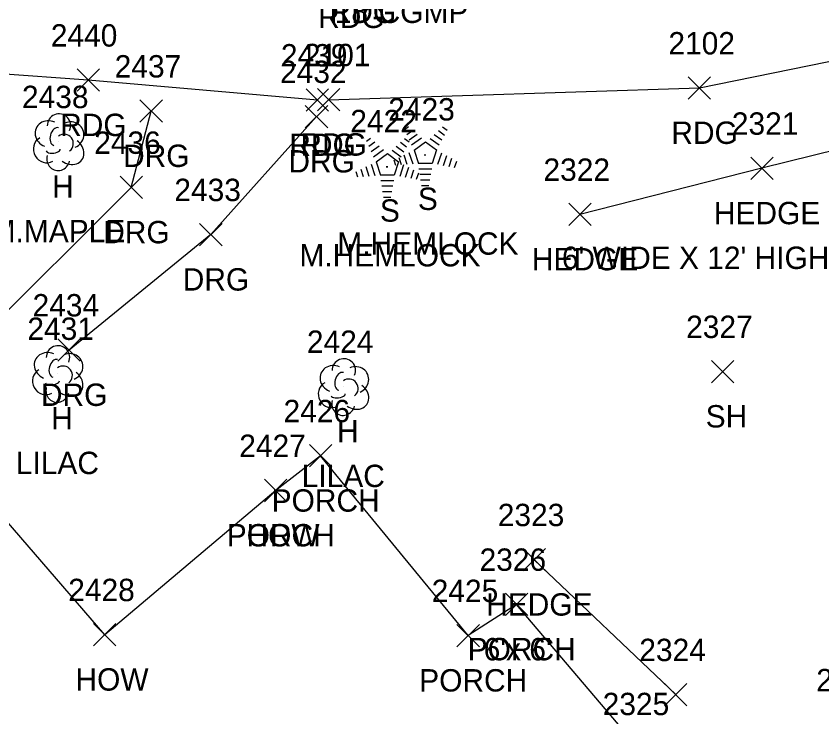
# Model space of a CAD drawing. Extents: x 1633660 to 1636532, y 388643 to 392631.
# Drawn here: x 1634467.3 to 1634539.4, y 389050.9 to 389113.6 of the extents above; entities that cross this region are included whole.
import ezdxf

# ---------------------------------------------------------------- set-up
doc = ezdxf.new("R2010")
doc.units = 0
for name, color, linetype in [('D_C', 7, 'Continuous'), ('L_A', 7, 'Continuous'), ('L_C', 7, 'Continuous'), ('L_I', 7, 'Continuous'), ('L_TIC', 7, 'Continuous'), ('LAHR', 7, 'Continuous'), ('LBC', 7, 'Continuous'), ('LBF', 7, 'Continuous'), ('LTC', 7, 'Continuous'), ('LTD', 7, 'Continuous'), ('P_A', 7, 'Continuous'), ('P_I', 7, 'Continuous'), ('P_TIC', 7, 'Continuous'), ('PEU', 7, 'Continuous'), ('R_A', 7, 'Continuous'), ('R_I', 7, 'Continuous'), ('R_TIC', 7, 'Continuous'), ('RDG', 7, 'Continuous')]:
    doc.layers.add(name, color=color, linetype=linetype)

msp = doc.modelspace()

# ---------------------------------------------------------------- linework, layer by layer
at = {"layer": 'L_TIC'}
for points in [[(1634533.001, 389098.978), (1634535.001, 389100.978)], [(1634535.001, 389098.978), (1634533.001, 389100.978)], [(1634516.729, 389094.857), (1634518.729, 389096.857)], [(1634518.729, 389094.857), (1634516.729, 389096.857)], [(1634529.482, 389080.803), (1634531.482, 389082.803)], [(1634531.482, 389080.803), (1634529.482, 389082.803)], [(1634493.546, 389073.274), (1634495.546, 389075.274)], [(1634495.546, 389073.274), (1634493.546, 389075.274)], [(1634489.534, 389070.168), (1634491.534, 389072.168)], [(1634491.534, 389070.168), (1634489.534, 389072.168)], [(1634489.534, 389070.168), (1634491.534, 389072.168)], [(1634491.534, 389070.168), (1634489.534, 389072.168)], [(1634512.643, 389063.979), (1634514.643, 389065.979)], [(1634514.643, 389063.979), (1634512.643, 389065.979)], [(1634511.072, 389059.984), (1634513.072, 389061.984)], [(1634513.072, 389059.984), (1634511.072, 389061.984)], [(1634474.247, 389057.274), (1634476.247, 389059.274)], [(1634476.247, 389057.274), (1634474.247, 389059.274)], [(1634506.739, 389057.192), (1634508.739, 389059.192)], [(1634508.739, 389057.192), (1634506.739, 389059.192)], [(1634525.295, 389051.911), (1634527.295, 389053.911)], [(1634527.295, 389051.911), (1634525.295, 389053.911)]]:
    msp.add_lwpolyline(points, dxfattribs=at)
at = {"layer": 'LAHR'}
for points in [[(1634592.826, 389104.54), (1634584.979, 389115.891), (1634550.04, 389103.955), (1634534.001, 389099.978), (1634517.729, 389095.857)], [(1634513.643, 389064.979), (1634526.295, 389052.911)]]:
    msp.add_lwpolyline(points, dxfattribs=at)
at = {"layer": 'LBC'}
msp.add_lwpolyline([(1634490.534, 389071.168), (1634475.247, 389058.274), (1634454.014, 389082.86), (1634453.252, 389083.423)], dxfattribs=at)
at = {"layer": 'LBF'}
msp.add_lwpolyline([(1634481.088, 389025.255), (1634487.775, 389017.978), (1634523.023, 389048.078), (1634512.072, 389060.984), (1634507.739, 389058.192), (1634494.546, 389074.274), (1634490.534, 389071.168)], dxfattribs=at)
at = {"layer": 'LTC'}
for p, q in [((1634502.05, 389103.46), (1634502.404, 389103.717)), ((1634502.259, 389102.994), (1634502.788, 389103.379)), ((1634505.077, 389103.352), (1634505.626, 389102.953)), ((1634505.448, 389103.7), (1634505.867, 389103.396)), ((1634498.656, 389102.413), (1634499.011, 389102.67)), ((1634502.054, 389102.653), (1634502.474, 389102.348)), ((1634502.469, 389102.529), (1634503.172, 389103.04)), ((1634502.678, 389102.063), (1634503.557, 389102.701)), ((1634504.335, 389102.655), (1634505.144, 389102.066)), ((1634504.706, 389103.004), (1634505.385, 389102.51)), ((1634498.866, 389101.947), (1634499.395, 389102.331)), ((1634499.075, 389101.481), (1634499.779, 389101.993)), ((1634501.312, 389101.956), (1634501.992, 389101.463)), ((1634501.683, 389102.305), (1634502.233, 389101.906)), ((1634502.903, 389101.608), (1634503.915, 389102.342)), ((1634503.915, 389102.342), (1634504.912, 389101.617)), ((1634499.285, 389101.016), (1634500.163, 389101.653)), ((1634499.509, 389100.561), (1634500.521, 389101.295)), ((1634500.521, 389101.295), (1634501.518, 389100.57)), ((1634500.941, 389101.608), (1634501.751, 389101.019)), ((1634501.993, 389101.172), (1634502.264, 389100.337)), ((1634502.448, 389101.389), (1634502.779, 389100.369)), ((1634502.903, 389101.608), (1634503.29, 389100.414)), ((1634504.912, 389101.617), (1634504.52, 389100.414)), ((1634505.349, 389101.346), (1634505.011, 389100.307)), ((1634505.794, 389101.096), (1634505.506, 389100.211)), ((1634499.055, 389100.341), (1634499.386, 389099.322)), ((1634499.509, 389100.561), (1634499.897, 389099.367)), ((1634501.082, 389100.739), (1634501.234, 389100.271)), ((1634501.518, 389100.57), (1634501.127, 389099.367)), ((1634501.537, 389100.956), (1634501.749, 389100.304)), ((1634501.956, 389100.299), (1634501.618, 389099.26)), ((1634504.52, 389100.414), (1634503.29, 389100.414)), ((1634506.238, 389100.846), (1634506.001, 389100.116)), ((1634506.682, 389100.596), (1634506.496, 389100.021)), ((1634497.689, 389099.692), (1634497.841, 389099.224)), ((1634498.144, 389099.908), (1634498.356, 389099.257)), ((1634498.599, 389100.125), (1634498.871, 389099.29)), ((1634502.4, 389100.049), (1634502.113, 389099.164)), ((1634502.845, 389099.799), (1634502.608, 389099.069)), ((1634504.482, 389099.914), (1634503.337, 389099.914)), ((1634501.127, 389099.367), (1634499.897, 389099.367)), ((1634501.089, 389098.867), (1634499.944, 389098.867)), ((1634503.289, 389099.548), (1634503.102, 389098.974)), ((1634504.398, 389099.414), (1634503.41, 389099.414)), ((1634504.315, 389098.914), (1634503.483, 389098.914)), ((1634501.005, 389098.367), (1634500.017, 389098.367)), ((1634504.231, 389098.414), (1634503.556, 389098.414)), ((1634500.921, 389097.867), (1634500.089, 389097.867)), ((1634500.837, 389097.367), (1634500.162, 389097.367))]:
    msp.add_line(p, q, dxfattribs=at)
at = {"layer": 'LTD'}
for p, q in [((1634471.113, 389102.361), (1634471.113, 389102.361)), ((1634471.113, 389102.361), (1634471.113, 389102.361)), ((1634471.028, 389081.634), (1634471.028, 389081.634)), ((1634471.028, 389081.634), (1634471.028, 389081.634)), ((1634496.58, 389080.473), (1634496.58, 389080.473)), ((1634496.58, 389080.473), (1634496.58, 389080.473))]:
    msp.add_line(p, q, dxfattribs=at)
for centre in [(1634471.159, 389103.795), (1634471.074, 389083.068), (1634496.627, 389081.907)]:
    msp.add_arc(centre, 1.047, 335.52715, 180.95627, dxfattribs=at)
for centre, major_axis, ratio, start_param, end_param in [((1634470.321, 389103.028), (1.21, -0.512), 0.895232, 1.570796, 4.712389), ((1634472.154, 389102.945), (-1.141, -0.483), 0.949671, 1.570796, 4.712389), ((1634470.904, 389102.82), (-0.208, -0.792), 0.645439, 3.141593, 6.283185), ((1634470.029, 389101.653), (0.584, -1.042), 0.959034, 3.141593, 6.283185), ((1634471.613, 389102.195), (-0.5, 0.667), 0.989748, 3.141593, 6.283185), ((1634472.113, 389101.528), (-1.09, 0.792), 0.841452, 1.570796, 4.712389), ((1634471.113, 389100.861), (0.265, 1.061), 0.942809, 1.570796, 4.712389), ((1634470.654, 389101.611), (-0.625, -0.083), 0.423636, 0, 3.141593), ((1634470.236, 389082.301), (1.21, -0.512), 0.895232, 1.570796, 4.712389), ((1634472.069, 389082.218), (-1.141, -0.483), 0.949671, 1.570796, 4.712389), ((1634470.819, 389082.093), (-0.208, -0.792), 0.645439, 3.141593, 6.283185), ((1634471.528, 389081.468), (-0.5, 0.667), 0.989748, 3.141593, 6.283185), ((1634495.788, 389081.139), (1.21, -0.512), 0.895232, 1.570796, 4.712389), ((1634497.622, 389081.056), (-1.141, -0.483), 0.949671, 1.570796, 4.712389), ((1634469.944, 389080.926), (0.584, -1.042), 0.959034, 3.141593, 6.283185), ((1634472.028, 389080.801), (-1.09, 0.792), 0.841452, 1.570796, 4.712389), ((1634496.372, 389080.931), (-0.208, -0.792), 0.645439, 3.141593, 6.283185), ((1634470.569, 389080.884), (-0.625, -0.083), 0.423636, 0, 3.141593), ((1634497.08, 389080.306), (-0.5, 0.667), 0.989748, 3.141593, 6.283185), ((1634471.028, 389080.134), (0.265, 1.061), 0.942809, 1.570796, 4.712389), ((1634495.497, 389079.764), (0.584, -1.042), 0.959034, 3.141593, 6.283185), ((1634497.58, 389079.639), (-1.09, 0.792), 0.841452, 1.570796, 4.712389), ((1634496.122, 389079.722), (-0.625, -0.083), 0.423636, 0, 3.141593), ((1634496.58, 389078.973), (0.265, 1.061), 0.942809, 1.570796, 4.712389)]:
    msp.add_ellipse(centre, major_axis=major_axis, ratio=ratio, start_param=start_param, end_param=end_param, dxfattribs=at)
at = {"layer": 'P_TIC'}
for points in [[(1634472.777, 389106.863), (1634474.777, 389108.863)], [(1634474.777, 389106.863), (1634472.777, 389108.863)], [(1634527.409, 389106.16), (1634529.409, 389108.16)], [(1634529.409, 389106.16), (1634527.409, 389108.16)], [(1634493.264, 389105.084), (1634495.264, 389107.084)], [(1634495.264, 389105.084), (1634493.264, 389107.084)], [(1634494.257, 389105.111), (1634496.257, 389107.111)], [(1634496.257, 389105.111), (1634494.257, 389107.111)]]:
    msp.add_lwpolyline(points, dxfattribs=at)
at = {"layer": 'PEU'}
for points in [[(1634494.264, 389106.084), (1634473.777, 389107.863), (1634424.229, 389111.439), (1634384.008, 389116.065), (1634330.868, 389124.165)], [(1634495.257, 389106.111), (1634528.409, 389107.16), (1634590.613, 389119.869), (1634599.406, 389112.18), (1634604.173, 389099.806)]]:
    msp.add_lwpolyline(points, dxfattribs=at)
at = {"layer": 'R_TIC'}
for points in [[(1634478.401, 389104.098), (1634480.401, 389106.098)], [(1634480.401, 389104.098), (1634478.401, 389106.098)], [(1634493.18, 389103.605), (1634495.18, 389105.605)], [(1634495.18, 389103.605), (1634493.18, 389105.605)], [(1634476.624, 389097.271), (1634478.624, 389099.271)], [(1634478.624, 389097.271), (1634476.624, 389099.271)], [(1634483.733, 389093.046), (1634485.733, 389095.046)], [(1634485.733, 389093.046), (1634483.733, 389095.046)], [(1634471.059, 389082.731), (1634473.059, 389084.731)], [(1634473.059, 389082.731), (1634471.059, 389084.731)]]:
    msp.add_lwpolyline(points, dxfattribs=at)
at = {"layer": 'RDG'}
for points in [[(1634463.903, 389084.605), (1634477.624, 389098.271), (1634479.401, 389105.098)], [(1634494.18, 389104.605), (1634484.733, 389094.046), (1634472.059, 389083.731)]]:
    msp.add_lwpolyline(points, dxfattribs=at)

# ---------------------------------------------------------------- texts
at = {"layer": 'D_C'}
msp.add_text('18"CGMP', height=2, dxfattribs=at).set_placement((1634495.808, 389112.973))
at = {"layer": 'L_A'}
for s, p in [('H', (1634470.546, 389097.361)), ('S', (1634503.24, 389096.252)), ('S', (1634499.847, 389095.204)), ('HEDGE', (1634529.702, 389094.978)), ('HEDGE', (1634513.429, 389090.857)), ('SH', (1634528.97, 389076.803)), ('H', (1634470.461, 389076.634)), ('H', (1634496.013, 389075.473)), ('PORCH', (1634490.168, 389069.274)), ('PORCH', (1634486.156, 389066.168)), ('HOW', (1634487.92, 389066.168)), ('HEDGE', (1634509.344, 389059.979)), ('PORCH', (1634507.694, 389055.984)), ('HOW', (1634472.633, 389053.274)), ('PORCH', (1634503.361, 389053.192))]:
    msp.add_text(s, height=2, dxfattribs=at).set_placement(p)
at = {"layer": 'L_C'}
for s, p in [('M.MAPLE', (1634465.05, 389093.361)), ('M.HEMLOCK', (1634496.043, 389092.252)), ('M.HEMLOCK', (1634492.65, 389091.204)), ("6' WIDE X 12' HIGH LILAC", (1634516.119, 389090.978)), ('LILAC', (1634467.303, 389072.634)), ('LILAC', (1634492.856, 389071.473)), ("6'x 6'", (1634509.123, 389055.979))]:
    msp.add_text(s, height=2, dxfattribs=at).set_placement(p)
at = {"layer": 'L_I'}
for s, p in [('2438', (1634467.853, 389105.361)), ('2423', (1634500.595, 389104.252)), ('2422', (1634497.201, 389103.204)), ('2321', (1634531.308, 389102.978)), ('2322', (1634514.469, 389098.857)), ('2431', (1634468.335, 389084.634)), ('2327', (1634527.222, 389084.803)), ('2424', (1634493.32, 389083.473)), ('2426', (1634491.231, 389077.274)), ('2427', (1634487.274, 389074.168)), ('2427', (1634487.274, 389074.168)), ('2323', (1634510.383, 389067.979)), ('2326', (1634508.757, 389063.984)), ('2428', (1634471.987, 389061.274)), ('2425', (1634504.479, 389061.192)), ('2324', (1634523.035, 389055.911)), ('2305', (1634538.854, 389053.215)), ('2325', (1634519.763, 389051.078))]:
    msp.add_text(s, height=2, dxfattribs=at).set_placement(p)
at = {"layer": 'LTC'}
for p in [(1634503.797, 389101.356), (1634500.404, 389100.308)]:
    msp.add_text('.', height=1.037, rotation=270, dxfattribs=at).set_placement(p)
at = {"layer": 'P_A'}
for p in [(1634495.352, 389112.978), (1634494.326, 389112.525), (1634471.265, 389102.863), (1634525.898, 389102.16), (1634491.752, 389101.084), (1634492.745, 389101.111)]:
    msp.add_text('RDG', height=2, dxfattribs=at).set_placement(p)
at = {"layer": 'P_I'}
for s, p in [('2440', (1634470.43, 389110.863)), ('2102', (1634525.638, 389110.16)), ('2439', (1634490.996, 389109.084)), ('2101', (1634493.052, 389109.111))]:
    msp.add_text(s, height=2, dxfattribs=at).set_placement(p)
at = {"layer": 'R_A'}
for p in [(1634476.889, 389100.098), (1634491.668, 389099.605), (1634475.113, 389093.271), (1634482.221, 389089.046), (1634469.547, 389078.731)]:
    msp.add_text('DRG', height=2, dxfattribs=at).set_placement(p)
at = {"layer": 'R_I'}
for s, p in [('2437', (1634476.141, 389108.098)), ('2432', (1634490.92, 389107.605)), ('2436', (1634474.309, 389101.271)), ('2433', (1634481.473, 389097.046)), ('2434', (1634468.799, 389086.731))]:
    msp.add_text(s, height=2, dxfattribs=at).set_placement(p)

doc.saveas('drawing.dxf')
